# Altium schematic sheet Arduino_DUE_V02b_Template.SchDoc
size Letter
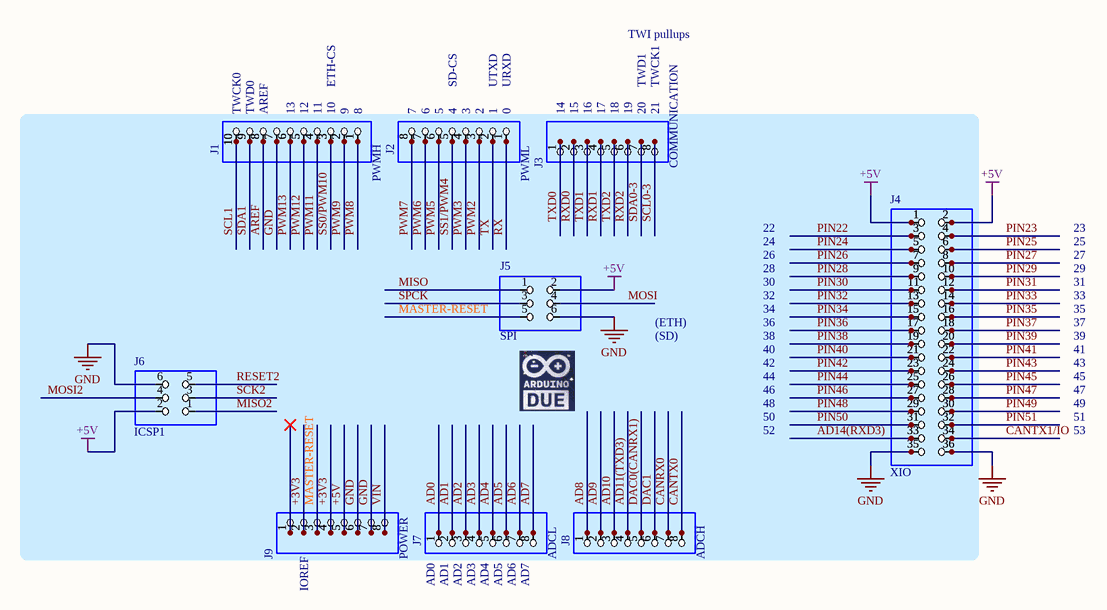
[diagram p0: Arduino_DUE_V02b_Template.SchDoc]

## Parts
J1  PWMH  [1X10]
J2  PWML  [1X08]
J3  COMMUNICATION  [1X08]
J4  XIO  [2X18]
J5  SPI  [2X03]
J6  ICSP1  [2X03]
J7  ADCL  [1X08]
J8  ADCH  [1X08]
J9  POWER  [1X08]

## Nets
+5V: J4.1 J4.2 J5.2 J6.2 J9.5
GND: J1.7 J4.35 J4.36 J5.6 J6.6 J9.6 J9.7
+3V3: J9.2 J9.4
AD0: J7.1
AD1: J7.2
AD2: J7.3
AD3: J7.4
AD4: J7.5
AD5: J7.6
AD6: J7.7
AD7: J7.8
AD8: J8.1
AD9: J8.2
AD10: J8.3
AD11(TXD3): J8.4
AD14(RXD3): J4.33
AREF: J1.8
CANRX0: J8.7
CANTX0: J8.8
CANTX1/IO: J4.34
DAC0(CANRX1): J8.5
DAC1: J8.6
MASTER-RESET: J5.5 J9.3
MISO: J5.1
MISO2: J6.1
MOSI: J5.4
MOSI2: J6.4
PIN22: J4.3
PIN23: J4.4
PIN24: J4.5
PIN25: J4.6
PIN26: J4.7
PIN27: J4.8
PIN28: J4.9
PIN29: J4.10
PIN30: J4.11
PIN31: J4.12
PIN32: J4.13
PIN33: J4.14
PIN34: J4.15
PIN35: J4.16
PIN36: J4.17
PIN37: J4.18
PIN38: J4.19
PIN39: J4.20
PIN40: J4.21
PIN41: J4.22
PIN42: J4.23
PIN43: J4.24
PIN44: J4.25
PIN45: J4.26
PIN46: J4.27
PIN47: J4.28
PIN48: J4.29
PIN49: J4.30
PIN50: J4.31
PIN51: J4.32
PWM2: J2.3
PWM3: J2.4
PWM5: J2.6
PWM6: J2.7
PWM7: J2.8
PWM8: J1.1
PWM9: J1.2
PWM11: J1.4
PWM12: J1.5
PWM13: J1.6
RESET2: J6.5
RX: J2.1
RXD0: J3.2
RXD1: J3.4
RXD2: J3.6
SCK2: J6.3
SCL0-3: J3.8
SCL1: J1.10
SDA0-3: J3.7
SDA1: J1.9
SPCK: J5.3
SS0/PWM10: J1.3
SS1/PWM4: J2.5
TX: J2.2
TXD0: J3.1
TXD1: J3.3
TXD2: J3.5
VIN: J9.8

Not connected (* = marked no-connect by the designer): J9 1*

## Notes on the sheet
- TWI pullups
- (near J1) TWCK0
- (near J1) TWD0
- (near J1) AREF
- (near J1) 13
- (near J1) 12
- (near J1) 11
- (near J1) 10
- (near J1) ETH-CS
- (near J1) 9
- (near J1) 8
- (near J2) 7
- (near J2) 6
- (near J2) 5
- (near J2) 4
- (near J2) SD-CS
- (near J2) 3
- (near J2) 2
- (near J2) 1
- (near J2) UTXD
- (near J2) 0
- (near J2) URXD
- 14
- 15
- (near J3) 16
- (near J3) 17
- (near J3) 18
- (near J3) 19
- (near J3) 20
- TWD1
- (near J3) 21
- TWCK1
- 22
- 24
- 26
- 28
- 23
- 25
- 27
- 29
- (ETH)
- (SD)
- 30
- 32
- 34
- 36
- 38
- 31
- 33
- 35
- 37
- 39
- 48
- 46
- 44
- 42
- 40
- 49
- 47
- 45
- 43
- 41
- 52
- 50
- 51
- 53
- (near J9) IOREF
- (near J7) AD0
- (near J7) AD1
- (near J7) AD2
- (near J7) AD3
- (near J7) AD4
- (near J7) AD5
- (near J7) AD6
- (near J7) AD7

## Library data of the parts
J1 = PINHD-1X10
J2 J3 J7-J9 = PINHD-1X8
J4 = PINHD-2X18
J5 J6 = PINHD-2X3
